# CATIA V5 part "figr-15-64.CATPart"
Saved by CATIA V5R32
Part number: Part1
Bounding box of the stored display mesh (mm): x -10 to 10, y -10 to 10, z 0 to 26
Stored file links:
  D:\PROJECTS\Project 2022\CATIA V5 6R 2022\Resources\Part Files\c15_catia_v5_6r2022_prt\figr-15-64.CATPart
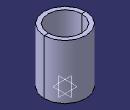
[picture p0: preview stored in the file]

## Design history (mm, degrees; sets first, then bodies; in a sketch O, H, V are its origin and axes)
SheetMetalParameters1: Thickness 2, BendRadius 4, KFactor 0.400515 {= log(min(100,max(20*SheetMetalParameters1.BendRadius,SheetMetalParameters1.Thickness)/SheetMetalParameters1.Thickness))/log(100)/2}, ReliefRadialLength 1, ReliefAxialLength 2, MinimumBendRadius 0
Body1 (main body)
  Sketch1 on xy-plane, origin (0, 0, 0), H (1, 0, 0), V (0, 1, 0)
    circle A1 centre (0, 0) radius 10
    radius A1 = 10
  d_RolledWall1: Extrude_Thickness 2, Extrude_Profile Sketch1, Extrude_StartLength 26, KFacteur 0.400515 {= SheetMetalParameters1.KFactor}, Extrude_EndLength 0, RolledWall_DeductionTable SheetMetalParameters1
